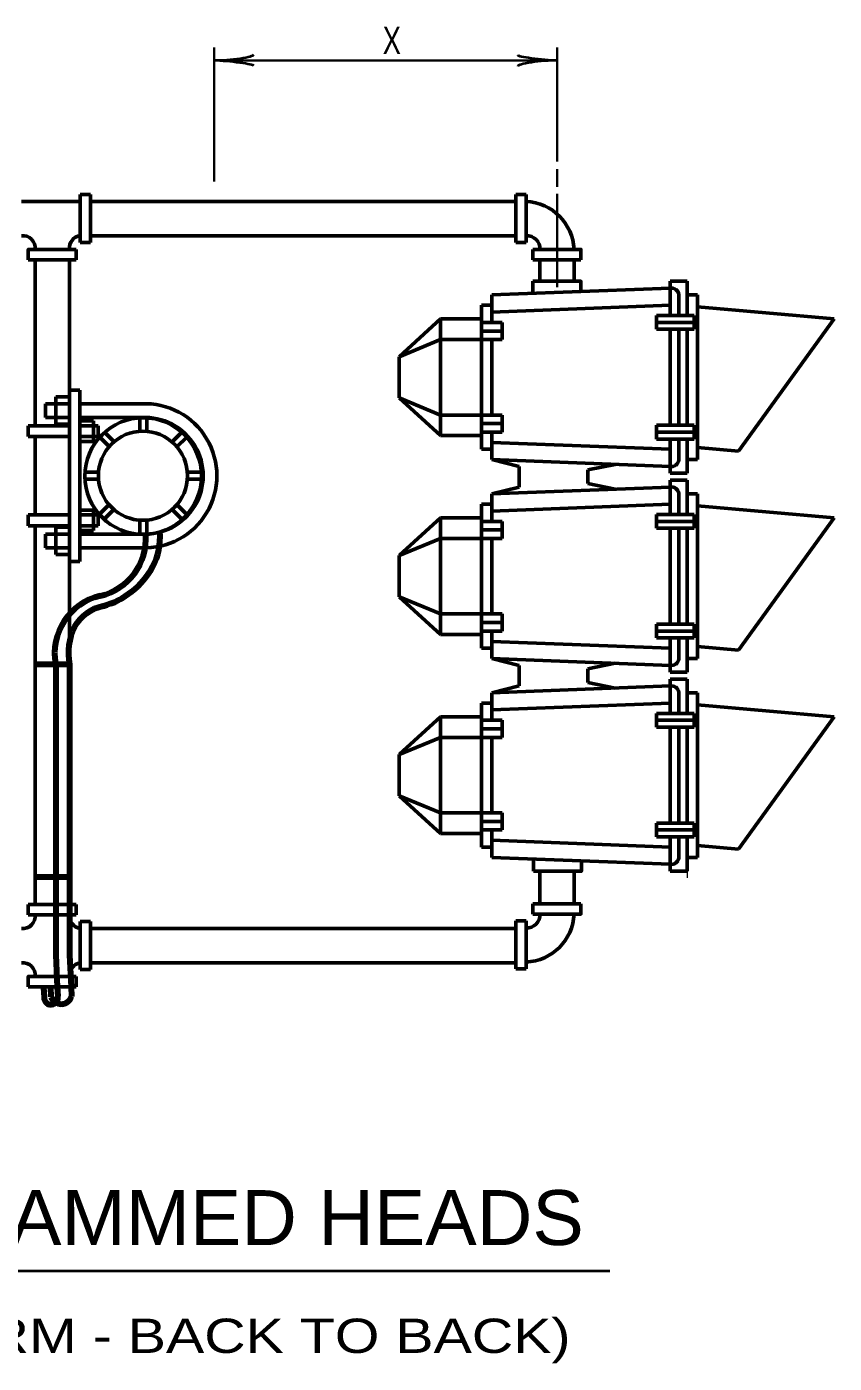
# Model space of a CAD drawing. Extents: x -370 to 486, y -203 to 341.
# Drawn here: x 186.5 to 257.2, y -16.9 to 100 of the extents above; entities that cross this region are included whole.
import ezdxf
from ezdxf.enums import TextEntityAlignment as Align

# ---------------------------------------------------------------- set-up
doc = ezdxf.new("R2010")
doc.units = 0
doc.header["$LTSCALE"] = 0.96
doc.layers.add('1', color=7, linetype='Continuous', lineweight=53)

msp = doc.modelspace()

# ---------------------------------------------------------------- linework, layer by layer
at = {"layer": '1', "lineweight": 35}
for p, q in [((202.9199, 98.1642), (202.9199, 86.455)), ((232.9199, 98.1642), (232.9199, 88.1796)), ((202.9199, 97.0382), (232.9199, 97.0382)), ((232.9199, 87.5354), (232.9199, 85.9652)), ((232.9199, 85.3613), (232.9199, 77.1884))]:
    msp.add_line(p, q, dxfattribs=at)
at = {"layer": '1'}
for p, q in [((186.0535, 84.703), (191.2011, 84.703)), ((191.2011, 85.303), (191.2011, 81.103)), ((191.2011, 85.303), (192.1011, 85.303)), ((192.1011, 85.303), (192.1011, 81.103)), ((192.1011, 84.703), (229.3011, 84.703)), ((229.3011, 85.303), (229.3011, 81.103)), ((230.2011, 85.303), (229.3011, 85.303)), ((230.2011, 85.303), (230.2011, 81.103)), ((191.2011, 81.103), (192.1011, 81.103)), ((192.1011, 81.703), (229.3011, 81.703)), ((230.2011, 81.103), (229.3011, 81.103)), ((190.8535, 79.603), (186.6535, 79.603)), ((187.2535, 79.603), (187.2535, 65.083)), ((190.2535, 79.603), (190.2535, 44.1978)), ((190.8535, 80.503), (190.8535, 79.603)), ((230.8011, 80.503), (230.8011, 79.603)), ((230.8011, 79.603), (235.0011, 79.603)), ((231.4011, 79.603), (231.4011, 77.7161)), ((234.4011, 79.603), (234.4011, 77.7161)), ((230.8011, 77.7161), (230.8011, 76.6546)), ((244.3011, 77.7161), (242.8011, 77.7161)), ((244.3011, 77.7161), (244.3011, 74.7161)), ((242.8011, 77.1161), (227.2011, 76.5161)), ((227.2011, 76.5161), (227.2011, 74.1161)), ((243.5511, 76.5614), (243.5511, 74.7161)), ((245.2011, 76.5161), (244.3011, 76.5161)), ((226.3011, 75.6161), (227.2011, 75.6161)), ((226.3011, 75.6161), (226.3011, 68.519)), ((242.8011, 75.6151), (227.2011, 75.0151)), ((245.2011, 75.4661), (257.1554, 74.4202)), ((222.7011, 74.4161), (219.1011, 71.1161)), ((222.7011, 74.4161), (222.7011, 64.2161)), ((222.7011, 74.4161), (226.3011, 74.4161)), ((226.3011, 74.1161), (228.1011, 74.1161)), ((228.1011, 74.1161), (228.1011, 72.6161)), ((244.9011, 74.7161), (241.6011, 74.7161)), ((241.6011, 74.7161), (241.6011, 73.5161)), ((241.6011, 74.1161), (244.9011, 74.1161)), ((244.9011, 74.7161), (244.9011, 73.5161)), ((257.1554, 74.4202), (248.7874, 62.8523)), ((219.1011, 71.1161), (222.7011, 72.6161)), ((222.7011, 72.6161), (228.1011, 72.6161)), ((226.3011, 73.3661), (228.1011, 73.3661)), ((227.2011, 72.6161), (227.2011, 68.519)), ((244.9011, 73.5161), (241.6011, 73.5161)), ((242.8011, 73.5161), (242.8011, 65.1161)), ((243.5511, 73.5161), (243.5511, 65.1161)), ((244.3011, 73.5161), (244.3011, 65.1161)), ((219.1011, 71.1161), (219.1011, 67.5161)), ((190.2535, 68.203), (191.1535, 68.203)), ((191.1535, 68.203), (191.1535, 53.203)), ((227.2011, 68.7161), (227.2011, 66.0161)), ((188.1535, 67.003), (188.1535, 65.803)), ((188.1535, 67.003), (190.2535, 67.003)), ((189.0535, 67.603), (190.2535, 67.603)), ((189.0535, 67.603), (189.0535, 65.203)), ((191.1535, 67.003), (196.5535, 67.003)), ((222.7011, 64.2161), (219.1011, 67.5161)), ((219.1011, 67.5161), (222.7011, 66.0161)), ((188.1535, 65.803), (190.2535, 65.803)), ((191.1535, 65.803), (196.5535, 65.803)), ((191.1535, 65.503), (192.3535, 65.503)), ((192.3535, 65.503), (192.3535, 63.703)), ((196.4139, 64.6042), (196.4139, 65.7776)), ((197.0139, 64.6042), (197.0139, 65.7776)), ((228.1011, 66.0161), (228.1011, 64.5161)), ((186.6535, 65.083), (190.2535, 65.083)), ((186.6535, 65.083), (186.6535, 64.123)), ((189.0535, 65.203), (190.2535, 65.203)), ((191.1535, 65.083), (192.7735, 65.083)), ((192.7735, 65.083), (192.7735, 64.123)), ((194.1545, 63.6872), (193.3287, 64.5129)), ((199.2408, 63.6672), (200.0917, 64.5134)), ((226.3011, 65.2661), (228.1011, 65.2661)), ((226.3011, 64.5161), (228.1011, 64.5161)), ((227.2011, 64.5161), (227.2011, 62.1161)), ((244.9011, 65.1161), (241.6011, 65.1161)), ((241.6011, 65.1161), (241.6011, 63.9161)), ((241.6011, 64.5161), (244.9011, 64.5161)), ((244.9011, 65.1161), (244.9011, 63.9161)), ((186.6535, 64.123), (190.2535, 64.123)), ((187.2535, 64.123), (187.2535, 57.283)), ((191.1535, 64.123), (192.7735, 64.123)), ((191.1535, 63.703), (192.3535, 63.703)), ((193.7302, 63.2629), (192.9044, 64.0886)), ((199.6639, 63.2417), (200.5148, 64.0879)), ((222.7011, 64.2161), (226.3011, 64.2161)), ((242.8011, 63.0172), (227.2011, 63.6172)), ((244.9011, 63.9161), (241.6011, 63.9161)), ((242.8011, 63.9161), (242.8011, 60.9161)), ((243.5511, 63.9161), (243.5511, 62.0708)), ((244.3011, 63.9161), (244.3011, 60.9161)), ((245.2011, 63.1661), (248.7874, 62.8523)), ((226.3011, 63.0161), (227.2011, 63.0161)), ((242.8011, 61.5161), (227.2011, 62.1161)), ((227.2011, 62.1161), (229.6023, 61.5161)), ((244.3011, 62.1161), (245.2011, 62.1161)), ((191.614, 61.003), (192.7871, 61.003)), ((200.5871, 61.003), (201.8138, 61.003)), ((229.6023, 61.5161), (229.6023, 59.7161)), ((238.0047, 61.7006), (235.6023, 61.2161)), ((235.6023, 61.2161), (235.6023, 60.0161)), ((244.3011, 60.9161), (242.8011, 60.9161)), ((191.614, 60.403), (192.7871, 60.403)), ((200.5871, 60.403), (201.8138, 60.403)), ((242.8011, 59.7162), (227.2011, 59.1161)), ((227.2011, 59.1161), (229.6023, 59.7161)), ((238.0047, 59.5317), (235.6023, 60.0161)), ((244.3011, 60.3161), (242.8011, 60.3161)), ((242.8011, 60.3161), (242.8011, 57.3161)), ((244.3011, 60.3161), (244.3011, 57.3161)), ((227.2011, 59.1161), (227.2011, 56.7161)), ((243.5511, 59.1615), (243.5511, 57.3162)), ((245.2011, 59.1161), (244.3011, 59.1161)), ((191.1535, 57.703), (192.3535, 57.703)), ((192.3535, 57.703), (192.3535, 55.903)), ((192.8595, 57.321), (193.7102, 58.167)), ((193.2826, 56.8955), (194.1333, 57.7415)), ((200.1218, 56.8731), (199.2464, 57.7482)), ((200.5459, 57.2974), (199.6705, 58.1725)), ((226.3011, 58.2161), (227.2011, 58.2161)), ((226.3011, 58.2161), (226.3011, 51.2071)), ((242.8011, 58.2151), (227.2011, 57.6151)), ((244.9011, 57.3161), (241.6011, 57.3161)), ((241.6011, 57.3161), (241.6011, 56.1161)), ((244.9011, 57.3161), (244.9011, 56.1161)), ((245.2011, 58.0661), (257.1554, 57.0202)), ((186.6535, 57.283), (190.2535, 57.283)), ((186.6535, 57.283), (186.6535, 56.323)), ((186.6535, 56.323), (190.2535, 56.323)), ((187.2535, 56.323), (187.2535, 23.1978)), ((189.0535, 56.203), (189.0535, 53.803)), ((189.0535, 56.203), (190.2535, 56.203)), ((191.1535, 57.283), (192.7735, 57.283)), ((191.1535, 56.323), (192.7735, 56.323)), ((192.7735, 57.283), (192.7735, 56.323)), ((196.4139, 55.5776), (196.4139, 56.8044)), ((197.0139, 55.5776), (197.0139, 56.8044)), ((222.7011, 57.0161), (219.1011, 53.7161)), ((222.7011, 57.0161), (222.7011, 46.8161)), ((222.7011, 57.0161), (226.3011, 57.0161)), ((226.3011, 56.7161), (228.1011, 56.7161)), ((228.1011, 56.7161), (228.1011, 55.2161)), ((241.6011, 56.7161), (244.9011, 56.7161)), ((257.1554, 57.0202), (248.7874, 45.4523)), ((188.1535, 55.603), (188.1535, 54.403)), ((188.1535, 55.603), (190.2535, 55.603)), ((191.1535, 55.903), (192.3535, 55.903)), ((191.1535, 55.603), (196.5535, 55.603)), ((219.1011, 53.7161), (222.7011, 55.2161)), ((222.7011, 55.2161), (226.3011, 55.2161)), ((226.3011, 55.9661), (228.1011, 55.9661)), ((226.3011, 55.2161), (228.1011, 55.2161)), ((227.2011, 55.2161), (227.2011, 51.0574)), ((244.9011, 56.1161), (241.6011, 56.1161)), ((242.8011, 56.1161), (242.8011, 47.7161)), ((243.5511, 56.1162), (243.5511, 47.7162)), ((244.3011, 56.1161), (244.3011, 47.7161)), ((188.1535, 54.403), (190.2535, 54.403)), ((189.0535, 53.803), (190.2535, 53.803)), ((191.1535, 54.403), (196.5535, 54.403)), ((190.2535, 53.203), (191.1535, 53.203)), ((219.1011, 53.7161), (219.1011, 50.1161)), ((226.3011, 51.3161), (226.3011, 45.6161)), ((227.2011, 51.3161), (227.2011, 48.6161)), ((222.7011, 46.8161), (219.1011, 50.1161)), ((219.1011, 50.1161), (222.7011, 48.6161)), ((222.7011, 48.6161), (226.3011, 48.6161)), ((226.3011, 48.6161), (228.1011, 48.6161)), ((228.1011, 48.6161), (228.1011, 47.1161)), ((222.7011, 46.8161), (226.3011, 46.8161)), ((226.3011, 47.8661), (228.1011, 47.8661)), ((226.3011, 47.1161), (228.1011, 47.1161)), ((227.2011, 47.1161), (227.2011, 44.7161)), ((244.9011, 47.7161), (241.6011, 47.7161)), ((241.6011, 47.7161), (241.6011, 46.5161)), ((241.6011, 47.1161), (244.9011, 47.1161)), ((244.9011, 47.7161), (244.9011, 46.5161)), ((226.3011, 45.6161), (227.2011, 45.6161)), ((242.8011, 45.6172), (227.2011, 46.2172)), ((244.9011, 46.5161), (241.6011, 46.5161)), ((242.8011, 46.5161), (242.8011, 43.5161)), ((243.5511, 46.5162), (243.5511, 44.6709)), ((244.3011, 46.5161), (244.3011, 43.5161)), ((245.2011, 45.7661), (248.7874, 45.4523)), ((242.8011, 44.1161), (227.2011, 44.7161)), ((227.2011, 44.7161), (229.6023, 44.1161)), ((244.3011, 44.7161), (245.2011, 44.7161)), ((229.6023, 44.1161), (229.6023, 42.3161)), ((238.0047, 44.3006), (235.6023, 43.8161)), ((235.6023, 43.8161), (235.6023, 42.6161)), ((244.3011, 43.5161), (242.8011, 43.5161)), ((242.8011, 42.3161), (227.2011, 41.7161)), ((227.2011, 41.7161), (229.6023, 42.3161)), ((238.0047, 42.1317), (235.6023, 42.6161)), ((244.3011, 42.9161), (242.8011, 42.9161)), ((242.8011, 42.9161), (242.8011, 39.9161)), ((244.3011, 42.9161), (244.3011, 39.9161)), ((227.2011, 41.7161), (227.2011, 39.3161)), ((243.5511, 41.7614), (243.5511, 39.9161)), ((245.2011, 41.7161), (244.3011, 41.7161)), ((226.3011, 40.8161), (227.2011, 40.8161)), ((226.3011, 40.8161), (226.3011, 33.8741)), ((242.8011, 40.8151), (227.2011, 40.2151)), ((244.9011, 39.9161), (241.6011, 39.9161)), ((241.6011, 39.9161), (241.6011, 38.7161)), ((244.9011, 39.9161), (244.9011, 38.7161)), ((245.2011, 40.6661), (257.1554, 39.6202)), ((222.7011, 39.6161), (219.1011, 36.3161)), ((222.7011, 39.6161), (222.7011, 29.4161)), ((222.7011, 39.6161), (226.3011, 39.6161)), ((226.3011, 39.3161), (228.1011, 39.3161)), ((228.1011, 39.3161), (228.1011, 37.8161)), ((241.6011, 39.3161), (244.9011, 39.3161)), ((244.9011, 38.7161), (241.6011, 38.7161)), ((242.8011, 38.7161), (242.8011, 30.3161)), ((243.5511, 38.7161), (243.5511, 30.3161)), ((244.3011, 38.7161), (244.3011, 30.3161)), ((257.1554, 39.6202), (248.7874, 28.0523)), ((219.1011, 36.3161), (222.7011, 37.8161)), ((222.7011, 37.8161), (226.3011, 37.8161)), ((226.3011, 38.5661), (228.1011, 38.5661)), ((226.3011, 37.8161), (228.1011, 37.8161)), ((227.2011, 37.8161), (227.2011, 33.8741)), ((219.1011, 36.3161), (219.1011, 32.7161)), ((226.3011, 33.9161), (226.3011, 28.2161)), ((227.2011, 33.9161), (227.2011, 31.2161)), ((222.7011, 29.4161), (219.1011, 32.7161)), ((219.1011, 32.7161), (222.7011, 31.2161)), ((222.7011, 31.2161), (226.3011, 31.2161)), ((226.3011, 31.2161), (228.1011, 31.2161)), ((226.3011, 30.4661), (228.1011, 30.4661)), ((228.1011, 31.2161), (228.1011, 29.7161)), ((222.7011, 29.4161), (226.3011, 29.4161)), ((226.3011, 29.7161), (228.1011, 29.7161)), ((227.2011, 29.7161), (227.2011, 27.3161)), ((244.9011, 30.3161), (241.6011, 30.3161)), ((241.6011, 30.3161), (241.6011, 29.1161)), ((241.6011, 29.7161), (244.9011, 29.7161)), ((244.9011, 30.3161), (244.9011, 29.1161)), ((226.3011, 28.2161), (227.2011, 28.2161)), ((242.8011, 28.2172), (227.2011, 28.8172)), ((244.9011, 29.1161), (241.6011, 29.1161)), ((242.8011, 29.1161), (242.8011, 26.1161)), ((243.5511, 29.1161), (243.5511, 27.2708)), ((244.3011, 29.1161), (244.3011, 26.1161)), ((245.2011, 28.3661), (248.7874, 28.0523)), ((242.8011, 26.7161), (227.2011, 27.3161)), ((230.8365, 26.1028), (230.8365, 27.1643)), ((244.3011, 27.3161), (245.2011, 27.3161)), ((231.4011, 23.2584), (231.4011, 26.1028)), ((234.4011, 23.2584), (234.4011, 26.1028)), ((244.3011, 26.1161), (242.8011, 26.1161)), ((190.2535, 25.5978), (190.2535, 23.1978)), ((190.8535, 23.1978), (186.6535, 23.1978)), ((186.6535, 22.2978), (186.6535, 23.1978)), ((190.8535, 22.2978), (186.6535, 22.2978)), ((190.8535, 22.2978), (190.8535, 23.1978)), ((230.8011, 23.2584), (235.0011, 23.2584)), ((230.8011, 22.3584), (230.8011, 23.2584)), ((191.2011, 17.4978), (191.2011, 21.6978)), ((191.2011, 21.6978), (192.1011, 21.6978)), ((192.1011, 17.4978), (192.1011, 21.6978)), ((192.1011, 21.0897), (229.3011, 21.0897)), ((229.3011, 17.5584), (229.3011, 21.7584)), ((230.2011, 21.7584), (229.3011, 21.7584)), ((230.2011, 17.5584), (230.2011, 21.7584)), ((192.1011, 18.0897), (229.3011, 18.0897)), ((230.2011, 17.5584), (229.3011, 17.5584)), ((190.8535, 16.9046), (190.8535, 16.0046)), ((191.2011, 17.4978), (192.1011, 17.4978)), ((190.8535, 16.0046), (186.6535, 16.0046))]:
    msp.add_line(p, q, dxfattribs=at)
at = {"layer": '1', "lineweight": 158}
for p, q in [((190.2535, 44.1978), (187.2535, 44.1978)), ((190.2535, 25.5978), (187.2535, 25.5978))]:
    msp.add_line(p, q, dxfattribs=at)
at = {"layer": '1', "lineweight": 106}
for p, q in [((189.0535, 44.1978), (189.0535, 18.751)), ((190.2535, 44.1978), (190.2535, 18.751)), ((189.0535, 18.751), (189.1975, 16.0046)), ((187.999, 15.9418), (188.0435, 15.0931)), ((188.5981, 15.9733), (188.6426, 15.1246)), ((189.1974, 16.0046), (189.2419, 15.1559))]:
    msp.add_line(p, q, dxfattribs=at)
at = {"layer": '1', "lineweight": 13}
msp.add_line((244.3011, 26.1161), (244.3011, 25.5161), dxfattribs=at)
at = {"layer": '1', "lineweight": 40}
msp.add_line((158.291, -8.8441), (237.5365, -8.8441), dxfattribs=at)
at = {"layer": '1'}
for points in [[(190.8535, 80.503), (186.6535, 80.503), (186.6535, 79.603)], [(230.8011, 80.503), (235.0011, 80.503), (235.0011, 79.603)], [(230.8011, 77.7161), (235.0011, 77.7161), (235.0011, 76.8161)], [(242.8011, 77.7161), (242.8011, 77.0313), (242.8011, 74.7161)], [(245.2011, 76.5161), (245.2011, 75.4661), (245.2011, 63.1661), (245.2011, 62.1161)], [(226.3011, 68.7161), (226.3011, 66.0161), (226.3011, 64.5161), (226.3011, 63.0161)], [(222.7011, 66.0161), (226.3011, 66.0161), (228.1011, 66.0161)], [(245.2011, 59.1161), (245.2011, 58.0661), (245.2011, 45.7661), (245.2011, 44.7161)], [(245.2011, 41.7161), (245.2011, 40.6661), (245.2011, 28.3661), (245.2011, 27.3161)], [(230.8365, 26.1028), (235.0365, 26.1028), (235.0365, 27.0028)], [(230.8011, 22.3584), (235.0011, 22.3584), (235.0011, 23.2584)], [(190.8535, 16.9046), (186.6535, 16.9046), (186.6535, 16.0046)]]:
    msp.add_lwpolyline(points, dxfattribs=at)
at = {"layer": '1', "lineweight": 106}
msp.add_lwpolyline([(190.2535, 18.751), (190.3974, 16.0046), (190.4419, 15.1559)], dxfattribs=at)
at = {"layer": '1'}
for centre, radius in [((196.7139, 60.6776), 5.1), ((196.6871, 60.7043), 3.9)]:
    msp.add_circle(centre, radius, dxfattribs=at)
for centre, radius, start, end in [((229.9775, 80.2794), 4.4293, 2.89399, 87.10601), ((186.1723, 80.6218), 1.0877, 353.73087, 96.26912), ((191.3347, 80.6218), 1.0877, 97.05633, 186.26913), ((230.2822, 80.5841), 1.1218, 355.85174, 94.14826), ((242.9153, 76.4861), 0.6403, 6.75399, 100.27275), ((196.8467, 60.703), 6.3068, 267.33556, 92.66444), ((196.8452, 60.703), 5.1083, 266.72684, 93.27315), ((242.9153, 62.1461), 0.6403, 259.72725, 353.24601), ((242.9153, 59.0862), 0.6403, 6.75399, 100.27275), ((242.9153, 44.7462), 0.6403, 259.72725, 353.24601), ((242.9153, 41.6861), 0.6403, 6.75399, 100.27275), ((242.9153, 27.3461), 0.6403, 259.72725, 353.24601), ((186.1723, 22.179), 1.0877, 263.73087, 6.26912), ((191.3541, 22.179), 1.0877, 173.73087, 261.91278), ((229.9775, 22.582), 4.4293, 272.89399, 357.10601), ((230.2822, 22.2773), 1.1218, 265.85174, 4.14826), ((186.1723, 17.0234), 1.0877, 353.73087, 96.26912), ((191.3541, 17.0234), 1.0877, 98.08722, 186.26913)]:
    msp.add_arc(centre, radius, start, end, dxfattribs=at)
at = {"layer": '1', "lineweight": 106}
for centre, radius, start, end in [((191.7898, 55.2217), 5.157, 283.04203, 4.15544), ((193.0234, 55.2542), 5.157, 331.17928, 5.68884), ((191.3901, 56.0221), 6.959, 284.84465, 332.12221), ((194.1172, 45.1739), 5.157, 103.04203, 190.91023), ((193.9468, 45.6562), 3.7205, 102.00348, 150.44345), ((195.3172, 45.1739), 5.157, 153.29385, 190.91023), ((188.6469, 15.0452), 0.6052, 175.46493, 10.53455), ((189.5371, 15.4375), 0.9476, 199.28082, 342.71237)]:
    msp.add_arc(centre, radius, start, end, dxfattribs=at)
at = {"layer": '1', "lineweight": 40}
for centre, major_axis, ratio, start_param, end_param in [((204.2293, 97.3698), (-2.1428, -0.1874), 0.122415, 0.89635335, 3.14159265), ((204.2293, 97.3698), (-2.1428, -0.1874), 0.122415, 0.89635335, 3.14159265), ((231.5753, 97.2921), (2.1077, -0.2108), 0.07063, 3.14071475, 5.41810995), ((204.2645, 96.7843), (-2.1077, 0.2108), 0.07063, 3.14071475, 5.41810995), ((204.2645, 96.7843), (-2.1077, 0.2108), 0.07063, 3.14071475, 5.41810995), ((231.6105, 96.7066), (2.1428, 0.1874), 0.122415, 0.89635335, 3.14159265)]:
    msp.add_ellipse(centre, major_axis=major_axis, ratio=ratio, start_param=start_param, end_param=end_param, dxfattribs=at)

# ---------------------------------------------------------------- texts
at = {"layer": '1'}
for s, height, width, p in [('X', 2.4, 0.75, (218.4553, 97.5832)), ('PROGRAMMED HEADS', 4.8, 1.05, (197.7977, -6.5913)), ('(MAST ARM - BACK TO BACK)', 3, 1.25, (198.4272, -16.032))]:
    msp.add_text(s, height=height, dxfattribs=dict(at, width=width)).set_placement(p, align=Align.CENTER)

doc.saveas('drawing.dxf')
